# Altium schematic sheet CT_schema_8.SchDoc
size 147 x 119 mm
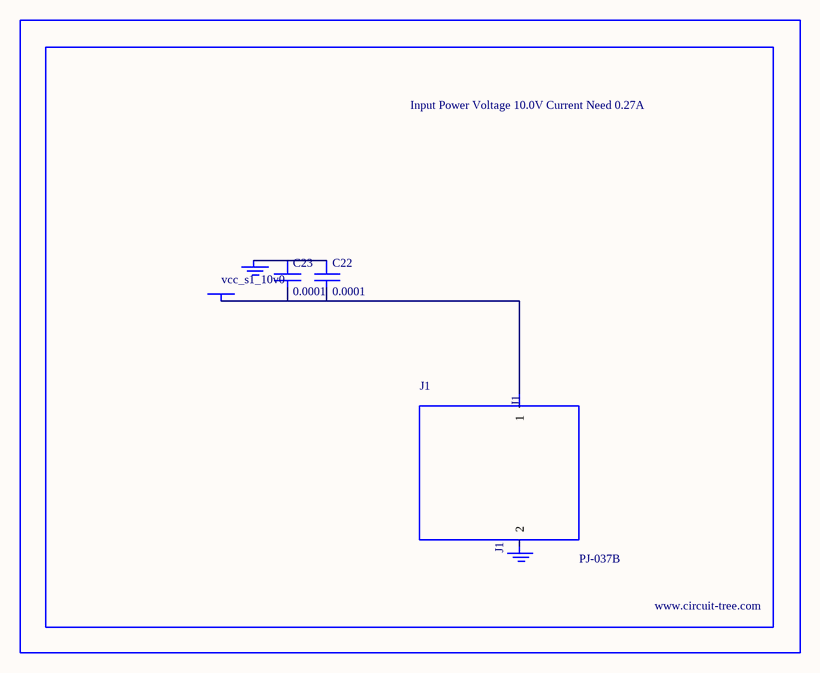
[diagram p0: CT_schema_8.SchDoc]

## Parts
BORDER7  (no value)
C22  0.0001  [EXV-9H]
C23  0.0001  [EXV-9H]
GND_INSTANCE_7_0  (no value)
GND_INSTANCE_7_1  (no value)
J1  PJ-037B  [PJ-037B_PACKAGE]
POWER_INSTANCE_7_0  vcc_s1_10v0

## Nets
NetC22_1: C22.1 C23.1 GND_INSTANCE_7_0.0(GND)
NetC22_2: C22.2 C23.2 J1.1 POWER_INSTANCE_7_0.0(PWR)

Not connected (* = marked no-connect by the designer): GND_INSTANCE_7_1 0(GND); J1 2

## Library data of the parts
BORDER7 = BORDER_PAGE7
C22 C23 = EDK107M035A9HAA
GND_INSTANCE_7_0 GND_INSTANCE_7_1 = GND
POWER_INSTANCE_7_0 = PWR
